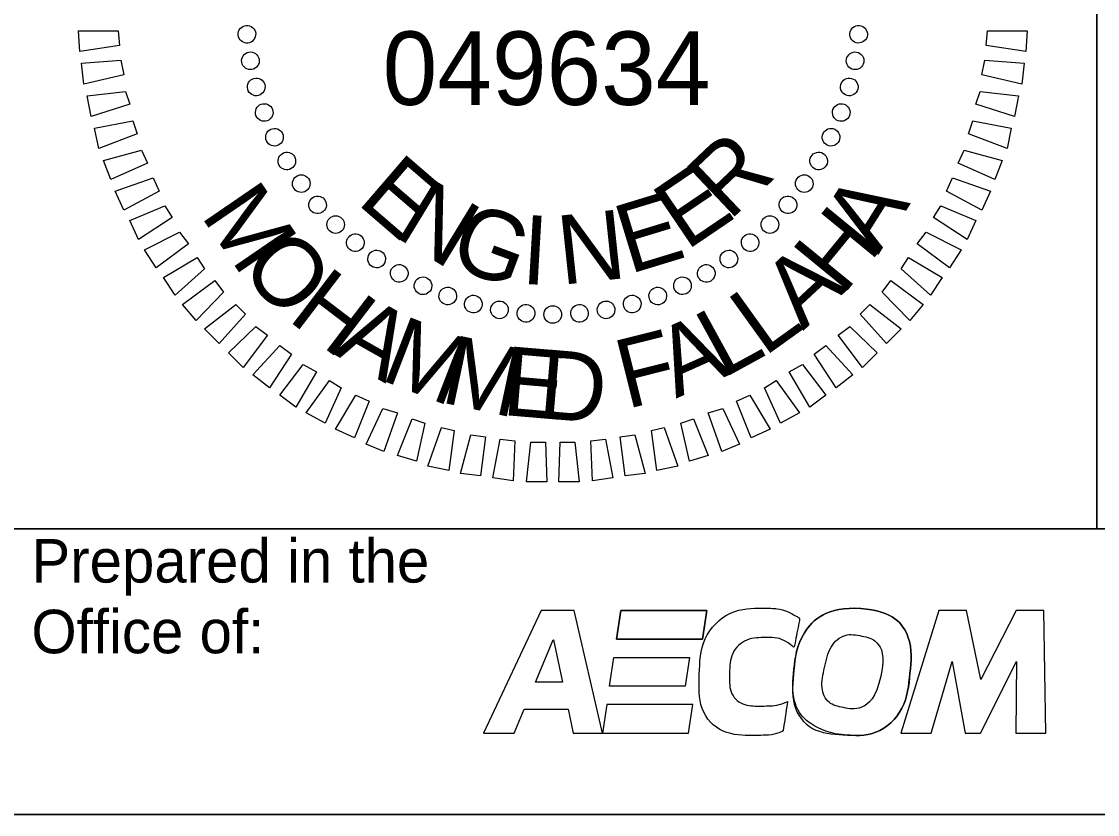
# Model space of a CAD drawing. Extents: x 2113883 to 2114903, y 714180 to 714840.
# Drawn here: x 2114763.5 to 2114822.8, y 714719.5 to 714763.2 of the extents above; entities that cross this region are included whole.
import ezdxf

# ---------------------------------------------------------------- set-up
doc = ezdxf.new("R2010")
doc.units = 0
for name, color, linetype in [('Default', 7, 'Continuous'), ('Prop DSN Text', 7, 'Continuous'), ('Sheet Block Title CELL', 7, 'Continuous'), ('Sheet Border Standard 30in CELL', 7, 'Continuous'), ('Sheet Professional Seal CELL', 7, 'Continuous'), ('Sheet Sticker Exception Certification CELL', 7, 'Continuous')]:
    doc.layers.add(name, color=color, linetype=linetype)

# ---------------------------------------------------------------- blocks, each defined once
blk = doc.blocks.new('block 3')
at = {"layer": 'Default'}
blk.add_open_spline([(0.122754, 0.093928), (0.12554, 0.09373), (0.127264, 0.091462), (0.126953, 0.088431), (0.126631, 0.085307), (0.12411, 0.082981), (0.121267, 0.083184), (0.118481, 0.083381), (0.116757, 0.085649), (0.117069, 0.088681), (0.11739, 0.091805), (0.119911, 0.094131), (0.122754, 0.093928)], degree=3, dxfattribs=at)
blk = doc.blocks.new('block 2')
at = {"layer": 'Default'}
for p, q in [((0.102337, 0.09375), (0.101973, 0.091327)), ((0.109658, 0.09375), (0.102337, 0.09375)), ((0.109295, 0.091327), (0.109658, 0.09375)), ((0.101973, 0.091327), (0.109295, 0.091327)), ((0.101374, 0.08733), (0.101738, 0.089754)), ((0.101738, 0.089754), (0.108181, 0.089754)), ((0.108181, 0.089754), (0.107817, 0.08733)), ((0.107817, 0.08733), (0.101374, 0.08733)), ((0.101138, 0.085757), (0.100775, 0.083333)), ((0.10846, 0.085757), (0.101138, 0.085757)), ((0.108096, 0.083333), (0.10846, 0.085757)), ((0.100775, 0.083333), (0.108096, 0.083333))]:
    blk.add_line(p, q, dxfattribs=at)
for points in [[(0.109295, 0.091327), (0.101973, 0.091327), (0.102337, 0.09375), (0.109658, 0.09375), (0.109295, 0.091327)], [(0.107817, 0.08733), (0.101374, 0.08733), (0.101738, 0.089754), (0.108181, 0.089754), (0.107817, 0.08733)], [(0.10846, 0.085757), (0.101138, 0.085757), (0.100775, 0.083333), (0.108096, 0.083333), (0.10846, 0.085757)]]:
    blk.add_lwpolyline(points, dxfattribs=at)
blk = doc.blocks.new('POINT_DISPLAY')
at = {"layer": 'Default'}
blk.add_line((0, 0), (0, 0), dxfattribs=at)

msp = doc.modelspace()

# ---------------------------------------------------------------- linework, layer by layer
at = {"layer": 'Prop DSN Text'}
for p, q in [((2114792.112, 714730.749), (2114788.936, 714723.999)), ((2114793.94, 714730.749), (2114792.112, 714730.749)), ((2114795.5, 714723.999), (2114793.94, 714730.749)), ((2114814.058, 714730.75), (2114811.961, 714723.999)), ((2114815.578, 714730.75), (2114814.058, 714730.75)), ((2114816.365, 714726.942), (2114815.578, 714730.75)), ((2114818.313, 714730.75), (2114816.365, 714726.942)), ((2114819.835, 714730.75), (2114818.313, 714730.75)), ((2114819.959, 714723.999), (2114819.835, 714730.75)), ((2114791.807, 714726.802), (2114792.787, 714729.143)), ((2114792.787, 714729.143), (2114792.802, 714729.143)), ((2114792.802, 714729.143), (2114793.299, 714726.802)), ((2114813.638, 714723.999), (2114814.78, 714727.951)), ((2114814.78, 714727.951), (2114815.497, 714723.999)), ((2114816.352, 714723.999), (2114818.33, 714727.949)), ((2114818.33, 714727.949), (2114818.307, 714723.999)), ((2114793.299, 714726.802), (2114791.807, 714726.802)), ((2114790.634, 714723.999), (2114791.185, 714725.314)), ((2114791.185, 714725.314), (2114793.615, 714725.314)), ((2114793.615, 714725.314), (2114793.894, 714723.999)), ((2114788.936, 714723.999), (2114790.634, 714723.999)), ((2114793.894, 714723.999), (2114795.5, 714723.999)), ((2114811.961, 714723.999), (2114813.638, 714723.999)), ((2114815.497, 714723.999), (2114816.352, 714723.999)), ((2114818.307, 714723.999), (2114819.959, 714723.999))]:
    msp.add_line(p, q, dxfattribs=at)
for points in [[(2114793.894, 714723.999), (2114795.5, 714723.999), (2114793.94, 714730.749), (2114792.112, 714730.749), (2114788.936, 714723.999), (2114790.634, 714723.999), (2114791.185, 714725.314), (2114793.615, 714725.314), (2114793.894, 714723.999)], [(2114819.959, 714723.999), (2114819.835, 714730.75), (2114818.313, 714730.75), (2114816.365, 714726.942), (2114815.578, 714730.75), (2114814.058, 714730.75), (2114811.961, 714723.999), (2114813.638, 714723.999), (2114814.78, 714727.951), (2114815.497, 714723.999), (2114816.352, 714723.999), (2114818.33, 714727.949), (2114818.307, 714723.999), (2114819.959, 714723.999)]]:
    msp.add_lwpolyline(points, dxfattribs=at)
for points in [[(2114805.708, 714725.73), (2114805.255, 714725.521), (2114804.579, 714725.487), (2114804.248, 714725.487), (2114803.18, 714725.487), (2114802.473, 714726.215), (2114802.509, 714727.298), (2114802.547, 714728.442), (2114803.411, 714729.262), (2114804.585, 714729.262), (2114805.14, 714729.262), (2114805.629, 714729.078), (2114806.067, 714728.708), (2114806.067, 714728.708), (2114806.392, 714730.324), (2114806.392, 714730.324), (2114805.721, 714730.719), (2114805.159, 714730.881), (2114804.456, 714730.881), (2114802.513, 714730.881), (2114800.909, 714729.262), (2114800.841, 714727.227), (2114800.776, 714725.254), (2114802.058, 714723.867), (2114803.964, 714723.867), (2114804.295, 714723.867), (2114805.011, 714723.902), (2114805.463, 714724.11), (2114805.463, 714724.11), (2114805.708, 714725.73), (2114805.708, 714725.73)], [(2114805.708, 714725.73), (2114805.255, 714725.521), (2114804.579, 714725.487), (2114804.248, 714725.487), (2114803.18, 714725.487), (2114802.473, 714726.215), (2114802.509, 714727.298), (2114802.547, 714728.442), (2114803.411, 714729.262), (2114804.585, 714729.262), (2114805.14, 714729.262), (2114805.629, 714729.078), (2114806.067, 714728.708), (2114806.067, 714728.708), (2114806.392, 714730.324), (2114806.392, 714730.324), (2114805.721, 714730.719), (2114805.159, 714730.881), (2114804.456, 714730.881), (2114802.513, 714730.881), (2114800.909, 714729.262), (2114800.841, 714727.227), (2114800.776, 714725.254), (2114802.058, 714723.867), (2114803.964, 714723.867), (2114804.295, 714723.867), (2114805.011, 714723.902), (2114805.463, 714724.11), (2114805.463, 714724.11), (2114805.708, 714725.73), (2114805.708, 714725.73)], [(2114808.077, 714724.028), (2114806.692, 714724.442), (2114805.884, 714725.769), (2114806.058, 714727.464), (2114806.266, 714729.489), (2114807.9, 714730.996), (2114809.742, 714730.865)], [(2114809.742, 714730.865), (2114811.548, 714730.736), (2114812.664, 714729.267), (2114812.463, 714727.302), (2114812.255, 714725.278), (2114810.621, 714723.771), (2114808.778, 714723.902), (2114808.531, 714723.92), (2114808.297, 714723.962), (2114808.077, 714724.028)], [(2114810.857, 714727.138), (2114811.102, 714728.279), (2114810.677, 714729.168), (2114809.815, 714729.344), (2114808.867, 714729.539), (2114808.005, 714728.813), (2114807.745, 714727.607), (2114807.499, 714726.465), (2114807.924, 714725.577), (2114808.786, 714725.4), (2114809.735, 714725.206), (2114810.597, 714725.932), (2114810.857, 714727.138)], [(2114810.857, 714727.138), (2114811.102, 714728.279), (2114810.677, 714729.168), (2114809.815, 714729.344), (2114808.867, 714729.539), (2114808.005, 714728.813), (2114807.745, 714727.607), (2114807.499, 714726.465), (2114807.924, 714725.577), (2114808.786, 714725.4), (2114809.735, 714725.206), (2114810.597, 714725.932), (2114810.857, 714727.138)]]:
    msp.add_open_spline(points, degree=3, dxfattribs=at)
at = {"layer": 'Sheet Block Title CELL'}
msp.add_lwpolyline([(2114762.734, 714735.256), (2114882.735, 714735.256), (2114882.735, 714719.507), (2114762.734, 714719.507)], close=True, dxfattribs=at)
at = {"layer": 'Sheet Border Standard 30in CELL'}
for points in [[(2114762.734, 714802.756), (2114822.764, 714802.756), (2114822.764, 714735.256), (2114762.734, 714735.256)], [(2114822.764, 714802.756), (2114882.765, 714802.756), (2114882.765, 714735.256), (2114822.764, 714735.256)]]:
    msp.add_lwpolyline(points, close=True, dxfattribs=at)
at = {"layer": 'Sheet Professional Seal CELL'}
for points in [[(2114768.865, 714761.913), (2114766.671, 714761.575), (2114766.603, 714762.722), (2114768.797, 714762.722)], [(2114816.731, 714762.722), (2114818.925, 714762.722), (2114818.858, 714761.575), (2114816.664, 714761.913)], [(2114769.1, 714760.292), (2114766.906, 714759.786), (2114766.772, 714760.933), (2114768.931, 714761.102)], [(2114816.596, 714761.102), (2114818.757, 714760.934), (2114818.621, 714759.786), (2114816.427, 714760.293)], [(2114769.438, 714758.671), (2114767.311, 714757.996), (2114767.075, 714759.144), (2114769.202, 714759.381)], [(2114816.326, 714759.381), (2114818.453, 714759.145), (2114818.216, 714757.996), (2114816.09, 714758.672)], [(2114769.843, 714757.051), (2114767.717, 714756.242), (2114767.48, 714757.355), (2114769.607, 714757.761)], [(2114815.921, 714757.761), (2114818.047, 714757.356), (2114817.812, 714756.242), (2114815.684, 714757.051)], [(2114770.417, 714755.431), (2114768.392, 714754.519), (2114767.986, 714755.566), (2114770.08, 714756.139)], [(2114815.449, 714756.14), (2114817.541, 714755.567), (2114817.137, 714754.52), (2114815.111, 714755.431)], [(2114771.059, 714753.879), (2114769.1, 714752.831), (2114768.628, 714753.879), (2114770.722, 714754.62)], [(2114814.807, 714754.62), (2114816.9, 714753.879), (2114816.427, 714752.832), (2114814.469, 714753.879)], [(2114771.768, 714752.426), (2114769.911, 714751.211), (2114769.438, 714752.257), (2114771.362, 714753.068)], [(2114814.165, 714753.068), (2114816.089, 714752.258), (2114815.618, 714751.212), (2114813.761, 714752.426)], [(2114772.679, 714750.975), (2114770.89, 714749.659), (2114770.249, 714750.637), (2114772.173, 714751.617)], [(2114813.356, 714751.617), (2114815.28, 714750.638), (2114814.638, 714749.659), (2114812.85, 714750.975)], [(2114773.556, 714749.591), (2114771.936, 714748.14), (2114771.295, 714749.118), (2114773.151, 714750.232)], [(2114812.376, 714750.232), (2114814.233, 714749.119), (2114813.592, 714748.14), (2114811.971, 714749.592)], [(2114774.604, 714748.309), (2114773.085, 714746.755), (2114772.342, 714747.634), (2114774.131, 714748.949)], [(2114811.398, 714748.95), (2114813.187, 714747.634), (2114812.444, 714746.756), (2114810.925, 714748.309)], [(2114775.818, 714747.093), (2114774.367, 714745.473), (2114773.557, 714746.283), (2114775.279, 714747.634)], [(2114810.25, 714747.634), (2114811.971, 714746.284), (2114811.162, 714745.473), (2114809.71, 714747.093)], [(2114777.033, 714745.946), (2114775.683, 714744.156), (2114774.873, 714744.967), (2114776.392, 714746.418)], [(2114809.136, 714746.418), (2114810.655, 714744.967), (2114809.845, 714744.156), (2114808.494, 714745.946)], [(2114778.35, 714744.899), (2114777.135, 714743.042), (2114776.224, 714743.752), (2114777.708, 714745.372)], [(2114807.819, 714745.372), (2114809.305, 714743.752), (2114808.393, 714743.042), (2114807.179, 714744.899)], [(2114779.734, 714743.921), (2114778.587, 714741.962), (2114777.708, 714742.637), (2114778.992, 714744.325)], [(2114806.537, 714744.325), (2114807.819, 714742.637), (2114806.942, 714741.962), (2114805.794, 714743.921)], [(2114781.084, 714743.042), (2114780.207, 714741.085), (2114779.161, 714741.659), (2114780.443, 714743.447)], [(2114805.085, 714743.448), (2114806.368, 714741.659), (2114805.322, 714741.085), (2114804.444, 714743.042)], [(2114782.637, 714742.299), (2114781.827, 714740.274), (2114780.781, 714740.747), (2114781.895, 714742.637)], [(2114803.634, 714742.637), (2114804.748, 714740.747), (2114803.701, 714740.274), (2114802.891, 714742.3)], [(2114784.19, 714741.659), (2114783.447, 714739.532), (2114782.469, 714739.936), (2114783.38, 714741.895)], [(2114802.148, 714741.895), (2114803.06, 714739.936), (2114802.081, 714739.532), (2114801.338, 714741.659)], [(2114785.709, 714741.085), (2114785.237, 714738.991), (2114784.19, 714739.296), (2114785, 714741.321)], [(2114787.329, 714740.679), (2114787.026, 714738.485), (2114785.877, 714738.722), (2114786.62, 714740.848)], [(2114798.908, 714740.848), (2114799.65, 714738.722), (2114798.503, 714738.485), (2114798.198, 714740.679)], [(2114800.528, 714741.321), (2114801.338, 714739.296), (2114800.292, 714738.991), (2114799.819, 714741.085)], [(2114789.051, 714740.342), (2114788.781, 714738.182), (2114787.666, 714738.316), (2114788.241, 714740.443)], [(2114797.287, 714740.443), (2114797.861, 714738.316), (2114796.747, 714738.182), (2114796.478, 714740.342)], [(2114790.671, 714740.105), (2114790.57, 714737.911), (2114789.456, 714738.08), (2114789.861, 714740.207)], [(2114792.359, 714740.039), (2114792.427, 714737.845), (2114791.313, 714737.845), (2114791.548, 714740.039)], [(2114793.979, 714740.039), (2114794.216, 714737.845), (2114793.102, 714737.845), (2114793.17, 714740.039)], [(2114795.667, 714740.208), (2114796.072, 714738.08), (2114794.959, 714737.911), (2114794.858, 714740.105)]]:
    msp.add_lwpolyline(points, close=True, dxfattribs=at)
for centre, major_axis in [((2114775.892, 714762.535), (-0.484, -0.042)), ((2114809.628, 714762.536), (0.484, -0.042)), ((2114776.085, 714761.071), (-0.479, -0.084)), ((2114809.435, 714761.071), (0.479, -0.084)), ((2114776.405, 714759.629), (-0.47, -0.126)), ((2114809.115, 714759.629), (0.47, -0.126)), ((2114776.849, 714758.22), (-0.457, -0.166)), ((2114808.671, 714758.22), (0.457, -0.166)), ((2114777.414, 714756.855), (-0.441, -0.205)), ((2114808.106, 714756.856), (0.441, -0.205)), ((2114778.096, 714755.545), (-0.421, -0.243)), ((2114807.424, 714755.545), (0.421, -0.243)), ((2114778.89, 714754.299), (-0.398, -0.279)), ((2114806.63, 714754.299), (0.398, -0.279)), ((2114779.789, 714753.127), (-0.372, -0.312)), ((2114805.731, 714753.128), (0.372, -0.312)), ((2114780.787, 714752.038), (-0.344, -0.344)), ((2114804.733, 714752.038), (0.344, -0.344)), ((2114781.876, 714751.04), (-0.312, -0.372)), ((2114803.644, 714751.041), (0.312, -0.372)), ((2114783.048, 714750.141), (-0.279, -0.398)), ((2114802.472, 714750.141), (0.279, -0.398)), ((2114784.294, 714749.347), (-0.243, -0.421)), ((2114801.226, 714749.348), (0.243, -0.421)), ((2114785.604, 714748.665), (-0.205, -0.441)), ((2114799.916, 714748.666), (0.205, -0.441)), ((2114786.969, 714748.1), (-0.166, -0.457)), ((2114798.551, 714748.1), (0.166, -0.457)), ((2114788.378, 714747.656), (-0.126, -0.47)), ((2114797.143, 714747.656), (0.126, -0.47)), ((2114789.82, 714747.336), (-0.084, -0.479)), ((2114791.284, 714747.143), (-0.042, -0.484)), ((2114792.76, 714747.079), (0, -0.486)), ((2114794.236, 714747.144), (0.042, -0.484)), ((2114795.7, 714747.336), (0.084, -0.479))]:
    msp.add_ellipse(centre, major_axis=major_axis, ratio=0.999708, dxfattribs=at)
at = {"layer": 'Sheet Sticker Exception Certification CELL'}
msp.add_line((2114762.734, 714719.507), (2114882.757, 714719.507), dxfattribs=at)

# ---------------------------------------------------------------- block references
at = {"layer": 'Prop DSN Text', "xscale": 648.001866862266, "yscale": 648.0018668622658, "rotation": 1.3379890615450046e-09}
for name in ['block 2', 'block 3']:
    msp.add_blockref(name, (2114730.197, 714669.999), dxfattribs=at)
at = {"layer": 'Sheet Professional Seal CELL', "xscale": 41.411959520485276, "yscale": 41.41195952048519, "rotation": 0.00042986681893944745}
for p in [(2114775.886, 714762.52), (2114809.643, 714762.52), (2114776.088, 714761.068), (2114809.439, 714761.069), (2114776.392, 714759.617), (2114809.136, 714759.618), (2114776.831, 714758.199), (2114808.698, 714758.199), (2114808.123, 714756.849), (2114807.448, 714755.532), (2114778.89, 714754.283), (2114806.638, 714754.283), (2114779.768, 714753.101), (2114805.761, 714753.101), (2114780.781, 714752.022), (2114804.748, 714752.022), (2114781.861, 714751.009), (2114803.667, 714751.01), (2114783.043, 714750.131), (2114802.486, 714750.131), (2114784.291, 714749.322), (2114801.237, 714749.322), (2114785.608, 714748.647), (2114799.921, 714748.647), (2114786.958, 714748.072), (2114798.571, 714748.072), (2114788.376, 714747.634), (2114797.153, 714747.634), (2114789.827, 714747.33), (2114791.278, 714747.128), (2114792.764, 714747.06), (2114794.249, 714747.128), (2114795.701, 714747.33)]:
    msp.add_blockref('POINT_DISPLAY', p, dxfattribs=at)

# ---------------------------------------------------------------- texts
at = {"layer": 'Prop DSN Text'}
for s, height, p in [('Prepared in the ', 2.40001, (2114764.007, 714732.296)), ('Office of:', 2.4, (2114764.007, 714728.396))]:
    msp.add_text(s, height=height, rotation=0, dxfattribs=at).set_placement(p)
at = {"layer": 'Sheet Professional Seal CELL'}
for s, height, rotation, p in [('049634', 4.0508, 0.00043, (2114783.379, 714758.638)), ('R', 3.807, 43.48184, (2114802.491, 714752.196)), ('E', 3.807, 319.27732, (2114781.892, 714753.239)), ('E', 3.807, 34.12452, (2114800.12, 714750.568)), ('N', 3.807, 328.63439, (2114783.923, 714751.446)), ('M', 3.807, 304.41113, (2114773.297, 714752.562)), ('A', 3.807, 57.87872, (2114810.71, 714750.349)), ('E', 3.807, 16.96729, (2114796.976, 714749.294)), ('G', 3.807, 339.50364, (2114786.893, 714749.836)), ('N', 3.807, 6.05682, (2114793.24, 714748.713)), ('H', 3.807, 50.68353, (2114808.753, 714748.08)), ('I', 3.807, 356.70163, (2114790.98, 714748.78)), ('O', 3.807, 313.50721, (2114775.41, 714749.53)), ('A', 3.807, 42.87926, (2114806.564, 714746.167)), ('H', 3.807, 322.66556, (2114778.083, 714746.805)), ('L', 3.807, 35.69399, (2114804.414, 714744.716)), ('A', 3.807, 330.54958, (2114780.597, 714744.932)), ('M', 3.807, 338.92584, (2114783.164, 714743.512)), ('L', 3.807, 28.72874, (2114802.154, 714743.534)), ('F', 3.807, 14.0832, (2114796.833, 714741.859)), ('A', 3.807, 23.98385, (2114799.553, 714742.436)), ('M', 3.807, 348.01683, (2114786.489, 714742.256)), ('E', 3.807, 355.14349, (2114789.911, 714741.547)), ('D', 3.807, 355.14349, (2114791.901, 714741.383))]:
    msp.add_text(s, height=height, rotation=rotation, dxfattribs=at).set_placement(p)

doc.saveas('drawing.dxf')
